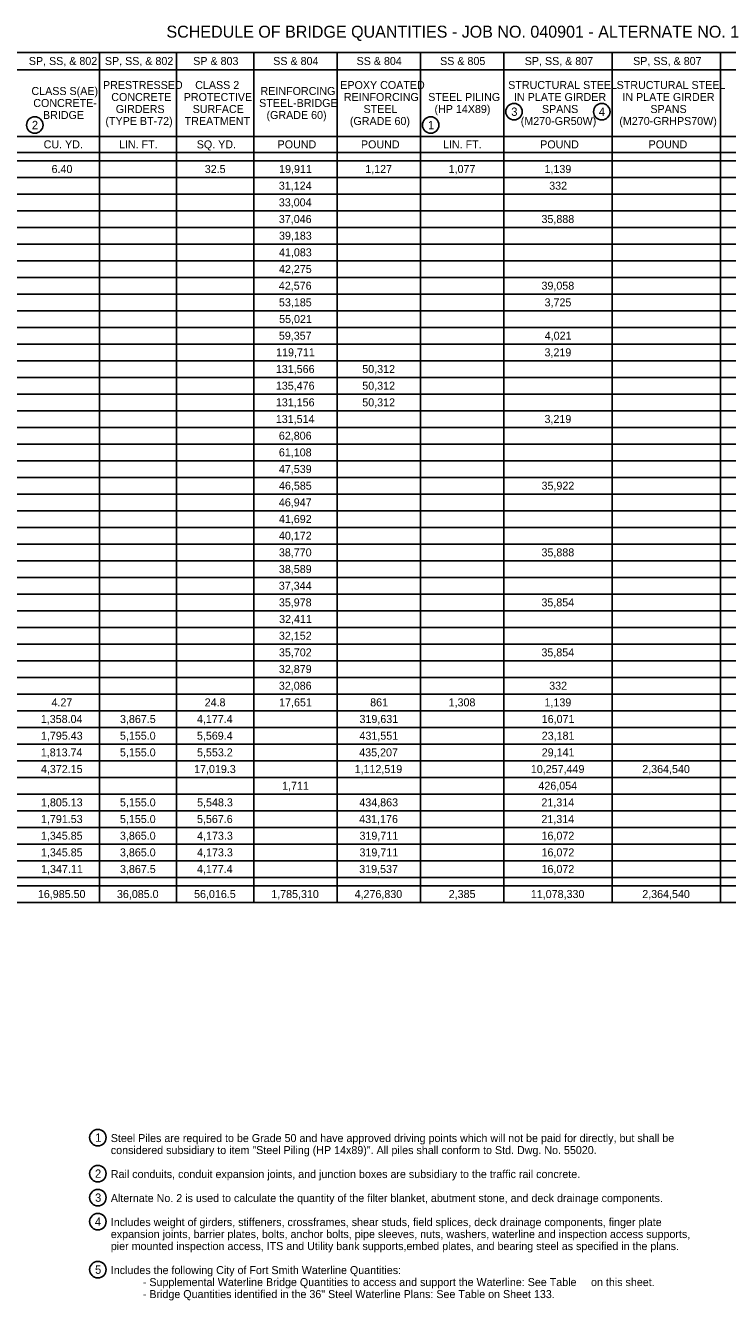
# Model space of a CAD drawing. Extents: x 0.06 to 1.38, y 0.04 to 0.85.
# Drawn here: x 0.468 to 0.907, y 0.057 to 0.854 of the extents above; entities that cross this region are included whole.
import ezdxf

# ---------------------------------------------------------------- set-up
doc = ezdxf.new("R2010")
doc.units = 0
for name, color, linetype in [('R_ROW', 7, 'Continuous'), ('R_Survey Control', 7, 'Continuous'), ('R_Wall', 7, 'Continuous')]:
    doc.layers.add(name, color=color, linetype=linetype)

msp = doc.modelspace()

# ---------------------------------------------------------------- linework, layer by layer
at = {"layer": 'R_Survey Control'}
for p, q in [((0.07508, 0.83695), (1.38207, 0.83695)), ((0.51421, 0.83695), (0.51421, 0.3057)), ((0.56236, 0.83695), (0.56236, 0.3057)), ((0.61051, 0.83695), (0.61051, 0.3057)), ((0.66259, 0.83695), (0.66259, 0.3057)), ((0.71468, 0.83695), (0.71468, 0.3057)), ((0.76676, 0.83695), (0.76676, 0.3057)), ((0.83447, 0.83695), (0.83447, 0.3057)), ((0.90222, 0.83695), (0.90222, 0.3057)), ((0.2593, 0.78445), (1.38207, 0.78445)), ((0.07508, 0.77445), (1.38207, 0.77445)), ((0.11154, 0.76924), (1.38207, 0.76924)), ((0.11154, 0.75883), (1.38207, 0.75883)), ((0.11154, 0.74841), (1.38207, 0.74841)), ((0.11154, 0.73799), (1.38207, 0.73799)), ((0.11154, 0.72758), (1.38207, 0.72758)), ((0.11154, 0.71716), (1.38207, 0.71716)), ((0.11154, 0.70674), (1.38207, 0.70674)), ((0.11154, 0.69633), (1.38207, 0.69633)), ((0.11154, 0.68591), (1.38207, 0.68591)), ((0.11154, 0.67549), (1.38207, 0.67549)), ((0.11154, 0.66508), (1.38207, 0.66508)), ((0.11154, 0.65466), (1.38207, 0.65466)), ((0.11154, 0.64424), (1.38207, 0.64424)), ((0.11154, 0.63383), (1.38207, 0.63383)), ((0.11154, 0.62341), (1.38207, 0.62341)), ((0.11154, 0.61299), (1.38207, 0.61299)), ((0.11154, 0.60258), (1.38207, 0.60258)), ((0.11154, 0.59216), (1.38207, 0.59216)), ((0.11154, 0.58174), (1.38207, 0.58174)), ((0.11154, 0.57133), (1.38207, 0.57133)), ((0.11154, 0.56091), (1.38207, 0.56091)), ((0.11154, 0.55049), (1.38207, 0.55049)), ((0.11154, 0.54008), (1.38207, 0.54008)), ((0.11154, 0.52966), (1.38207, 0.52966)), ((0.11154, 0.51924), (1.38207, 0.51924)), ((0.11154, 0.50883), (1.38207, 0.50883)), ((0.11154, 0.49841), (1.38207, 0.49841)), ((0.11154, 0.48799), (1.38207, 0.48799)), ((0.11154, 0.47758), (1.38207, 0.47758)), ((0.11154, 0.46716), (1.38207, 0.46716)), ((0.11154, 0.45674), (1.38207, 0.45674)), ((0.11154, 0.44633), (1.38207, 0.44633)), ((0.11154, 0.43591), (1.38207, 0.43591)), ((0.11154, 0.42549), (1.38207, 0.42549)), ((0.11154, 0.41508), (1.38207, 0.41508)), ((0.11154, 0.40466), (1.38207, 0.40466)), ((0.11154, 0.39424), (1.38207, 0.39424)), ((0.11154, 0.38383), (1.38207, 0.38383)), ((0.11154, 0.37341), (1.38207, 0.37341)), ((0.11154, 0.36299), (1.38207, 0.36299)), ((0.11154, 0.35258), (1.38207, 0.35258)), ((0.11154, 0.34216), (1.38207, 0.34216)), ((0.11154, 0.33174), (1.38207, 0.33174)), ((0.11154, 0.32133), (1.38207, 0.32133)), ((0.07508, 0.31612), (1.38207, 0.31612)), ((0.07508, 0.3057), (1.38207, 0.3057))]:
    msp.add_line(p, q, dxfattribs=at)
msp.add_lwpolyline([(0.2593, 0.82612), (0.30758, 0.82612), (0.41883, 0.82612), (0.46733, 0.82612), (0.509, 0.82612), (0.60403, 0.82612), (0.64048, 0.82612), (0.68476, 0.82612), (0.72903, 0.82612), (0.79673, 0.82612), (0.84248, 0.82612), (0.89457, 0.82612), (0.99353, 0.82612), (1.05082, 0.82612), (1.11332, 0.82612), (1.1813, 0.82612), (1.249, 0.82612), (1.249, 0.82612), (1.30109, 0.82612), (1.38207, 0.82612)], dxfattribs=at)
at = {"layer": 'R_Wall'}
for centre in [(0.77317, 0.79986), (0.828, 0.79986), (0.47374, 0.79152), (0.72109, 0.79152), (0.51317, 0.15868), (0.51317, 0.13618), (0.51317, 0.12118), (0.51317, 0.10618), (0.51317, 0.07618)]:
    msp.add_circle(centre, 0.00515, dxfattribs=at)

# ---------------------------------------------------------------- texts
at = {"layer": 'R_ROW'}
msp.add_text('SCHEDULE OF BRIDGE QUANTITIES - JOB NO. 040901 - ALTERNATE NO. 1', height=0.0075, dxfattribs=at).set_placement((0.55601, 0.84612))
at = {"layer": 'R_Survey Control'}
for s, p in [('SP, SS, & 802', (0.47003, 0.82904)), ('SP, SS, & 802', (0.51755, 0.82904)), ('SP & 803', (0.57273, 0.82904)), ('SS & 804', (0.62272, 0.82904)), ('SS & 804', (0.6748, 0.82904)), ('SS & 805', (0.72698, 0.82904)), ('SP, SS, & 807', (0.77985, 0.82904)), ('SP, SS, & 807', (0.84758, 0.82904)), ('CLASS S(AE)', (0.47167, 0.81029)), ('PRESTRESSED', (0.51636, 0.81404)), ('CLASS 2', (0.57397, 0.81404)), ('REINFORCING', (0.61478, 0.81029)), ('EPOXY COATED', (0.66461, 0.81404)), ('STRUCTURAL STEEL', (0.76952, 0.81404)), ('STRUCTURAL STEEL', (0.83725, 0.81404)), ('CONCRETE-', (0.47282, 0.80279)), ('CONCRETE', (0.52154, 0.80654)), ('PROTECTIVE', (0.56681, 0.80654)), ('STEEL-BRIDGE', (0.61393, 0.80279)), ('REINFORCING', (0.66686, 0.80654)), ('STEEL PILING', (0.71956, 0.80654)), ('IN PLATE GIRDER', (0.77313, 0.80654)), ('IN PLATE GIRDER', (0.84085, 0.80654)), ('BRIDGE', (0.47888, 0.79529)), ('GIRDERS', (0.52435, 0.79904)), ('SURFACE', (0.5724, 0.79904)), ('(GRADE 60)', (0.61852, 0.79529)), ('STEEL', (0.67915, 0.79904)), ('(HP 14X89)', (0.72347, 0.79904)), ('SPANS', (0.79062, 0.79904)), ('SPANS', (0.85835, 0.79904)), ('(TYPE BT-72)', (0.51791, 0.79154)), ('TREATMENT', (0.56741, 0.79154)), ('(GRADE 60)', (0.67061, 0.79154)), ('(M270-GR50W)', (0.77736, 0.79154)), ('(M270-GRHPS70W)', (0.83895, 0.79154)), ('CU. YD.', (0.4793, 0.77695)), ('LIN. FT.', (0.52636, 0.77695)), ('SQ. YD.', (0.57494, 0.77695)), ('POUND', (0.62545, 0.77695)), ('POUND', (0.67753, 0.77695)), ('LIN. FT.', (0.7288, 0.77695)), ('POUND', (0.78951, 0.77695)), ('POUND', (0.85724, 0.77695)), ('6.40', (0.48424, 0.76154)), ('32.5', (0.57994, 0.76154)), ('19,911', (0.62641, 0.76154)), ('1,127', (0.68021, 0.76154)), ('1,077', (0.7323, 0.76154)), ('1,139', (0.79221, 0.76154)), ('31,124', (0.62622, 0.75112)), ('332', (0.79514, 0.75112)), ('33,004', (0.62622, 0.7407)), ('37,046', (0.62624, 0.73029)), ('35,888', (0.79032, 0.73029)), ('39,183', (0.62633, 0.71987)), ('41,083', (0.62633, 0.70945)), ('42,275', (0.62631, 0.69904)), ('42,576', (0.62624, 0.68862)), ('39,058', (0.79032, 0.68862)), ('53,185', (0.62631, 0.6782)), ('3,725', (0.79225, 0.6782)), ('55,021', (0.62641, 0.66779)), ('59,357', (0.62625, 0.65737)), ('4,021', (0.79235, 0.65737)), ('119,711', (0.62453, 0.64695)), ('3,219', (0.79221, 0.64695)), ('131,566', (0.62437, 0.63654)), ('50,312', (0.67837, 0.63654)), ('135,476', (0.62437, 0.62612)), ('50,312', (0.67837, 0.62612)), ('131,156', (0.62437, 0.6157)), ('50,312', (0.67837, 0.6157)), ('131,514', (0.62434, 0.60529)), ('3,219', (0.79221, 0.60529)), ('62,806', (0.62624, 0.59487)), ('61,108', (0.62625, 0.58445)), ('47,539', (0.62627, 0.57404)), ('46,585', (0.62631, 0.56362)), ('35,922', (0.79035, 0.56362)), ('46,947', (0.62625, 0.5532)), ('41,692', (0.62628, 0.54279)), ('40,172', (0.62628, 0.53237)), ('38,770', (0.62627, 0.52195)), ('35,888', (0.79032, 0.52195)), ('38,589', (0.62627, 0.51154)), ('37,344', (0.62622, 0.50112)), ('35,978', (0.62625, 0.4907)), ('35,854', (0.79028, 0.4907)), ('32,411', (0.62641, 0.48029)), ('32,152', (0.62628, 0.46987)), ('35,702', (0.62628, 0.45945)), ('35,854', (0.79028, 0.45945)), ('32,879', (0.62627, 0.44904)), ('32,086', (0.62624, 0.43862)), ('332', (0.79514, 0.43862)), ('4.27', (0.48422, 0.4282)), ('24.8', (0.57989, 0.4282)), ('17,651', (0.62641, 0.4282)), ('861', (0.68329, 0.4282)), ('1,308', (0.7323, 0.4282)), ('1,139', (0.79221, 0.4282)), ('1,358.04', (0.47752, 0.41779)), ('3,867.5', (0.527, 0.41779)), ('4,177.4', (0.57506, 0.41779)), ('319,631', (0.67662, 0.41779)), ('16,071', (0.79047, 0.41779)), ('1,795.43', (0.47763, 0.40737)), ('5,155.0', (0.52696, 0.40737)), ('5,569.4', (0.57506, 0.40737)), ('431,551', (0.67662, 0.40737)), ('23,181', (0.79047, 0.40737)), ('1,813.74', (0.47752, 0.39695)), ('5,155.0', (0.52696, 0.39695)), ('5,553.2', (0.57512, 0.39695)), ('435,207', (0.67646, 0.39695)), ('29,141', (0.79047, 0.39695)), ('4,372.15', (0.47761, 0.38654)), ('17,019.3', (0.57329, 0.38654)), ('1,112,519', (0.67356, 0.38654)), ('10,257,449', (0.78367, 0.38654)), ('2,364,540', (0.85327, 0.38654)), ('1,711', (0.62828, 0.37612)), ('426,054', (0.7884, 0.37612)), ('1,805.13', (0.47763, 0.3657)), ('5,155.0', (0.52696, 0.3657)), ('5,548.3', (0.57517, 0.3657)), ('434,863', (0.67653, 0.3657)), ('21,314', (0.79028, 0.3657)), ('1,791.53', (0.47763, 0.35529)), ('5,155.0', (0.52696, 0.35529)), ('5,567.6', (0.57509, 0.35529)), ('431,176', (0.67645, 0.35529)), ('21,314', (0.79028, 0.35529)), ('1,345.85', (0.47761, 0.34487)), ('3,865.0', (0.52696, 0.34487)), ('4,173.3', (0.57517, 0.34487)), ('319,711', (0.67662, 0.34487)), ('16,072', (0.79035, 0.34487)), ('1,345.85', (0.47761, 0.33445)), ('3,865.0', (0.52696, 0.33445)), ('4,173.3', (0.57517, 0.33445)), ('319,711', (0.67662, 0.33445)), ('16,072', (0.79035, 0.33445)), ('1,347.11', (0.47771, 0.32404)), ('3,867.5', (0.527, 0.32404)), ('4,177.4', (0.57506, 0.32404)), ('319,537', (0.67646, 0.32404)), ('16,072', (0.79035, 0.32404)), ('16,985.50', (0.47569, 0.30841)), ('36,085.0', (0.52508, 0.30841)), ('56,016.5', (0.57327, 0.30841)), ('1,785,310', (0.62148, 0.30841)), ('4,276,830', (0.67356, 0.30841)), ('2,385', (0.73235, 0.30841)), ('11,078,330', (0.78366, 0.30841)), ('2,364,540', (0.85327, 0.30841))]:
    msp.add_text(s, height=0.005, dxfattribs=at).set_placement(p)
at = {"layer": 'R_Wall'}
for s, height, p in [('3', 0.00521, (0.77142, 0.79725)), ('4', 0.00521, (0.82614, 0.79725)), ('2', 0.00521, (0.47194, 0.78892)), ('1', 0.00521, (0.71942, 0.78892)), ('1', 0.00521, (0.51151, 0.15608)), ('Steel Piles are required to be Grade 50 and have approved driving points which will not be paid for directly, but shall be ', 0.005, (0.52126, 0.1559)), ('considered subsidiary to item "Steel Piling (HP 14x89)". All piles shall conform to Std. Dwg. No. 55020.', 0.005, (0.52126, 0.1484)), ('2', 0.00521, (0.51138, 0.13358)), ('Rail conduits, conduit expansion joints, and junction boxes are subsidiary to the traffic rail concrete.', 0.005, (0.52126, 0.1334)), ('3', 0.00521, (0.51142, 0.11858)), ('Alternate No. 2 is used to calculate the quantity of the filter blanket, abutment stone, and deck drainage components.', 0.005, (0.52126, 0.1184)), ('4', 0.00521, (0.51131, 0.10358)), ('Includes weight of girders, stiffeners, crossframes, shear studs, field splices, deck drainage components, finger plate ', 0.005, (0.52126, 0.1034)), ('expansion joints, barrier plates, bolts, anchor bolts, pipe sleeves, nuts, washers, waterline and inspection access supports, ', 0.005, (0.52126, 0.0959)), ('pier mounted inspection access, ITS and Utility bank supports,embed plates, and bearing steel as specified in the plans.', 0.005, (0.52126, 0.0884)), ('5', 0.00521, (0.51141, 0.07358)), ('Includes the following City of Fort Smith Waterline Quantities:', 0.005, (0.52126, 0.0734)), ('- Supplemental Waterline Bridge Quantities to access and support the Waterline: See Table ', 0.005, (0.54126, 0.0659)), ('on this sheet.', 0.005, (0.82126, 0.0659)), ('- Bridge Quantities identified in the 36" Steel Waterline Plans: See Table on Sheet 133.', 0.005, (0.54126, 0.0584))]:
    msp.add_text(s, height=height, dxfattribs=at).set_placement(p)

doc.saveas('drawing.dxf')
